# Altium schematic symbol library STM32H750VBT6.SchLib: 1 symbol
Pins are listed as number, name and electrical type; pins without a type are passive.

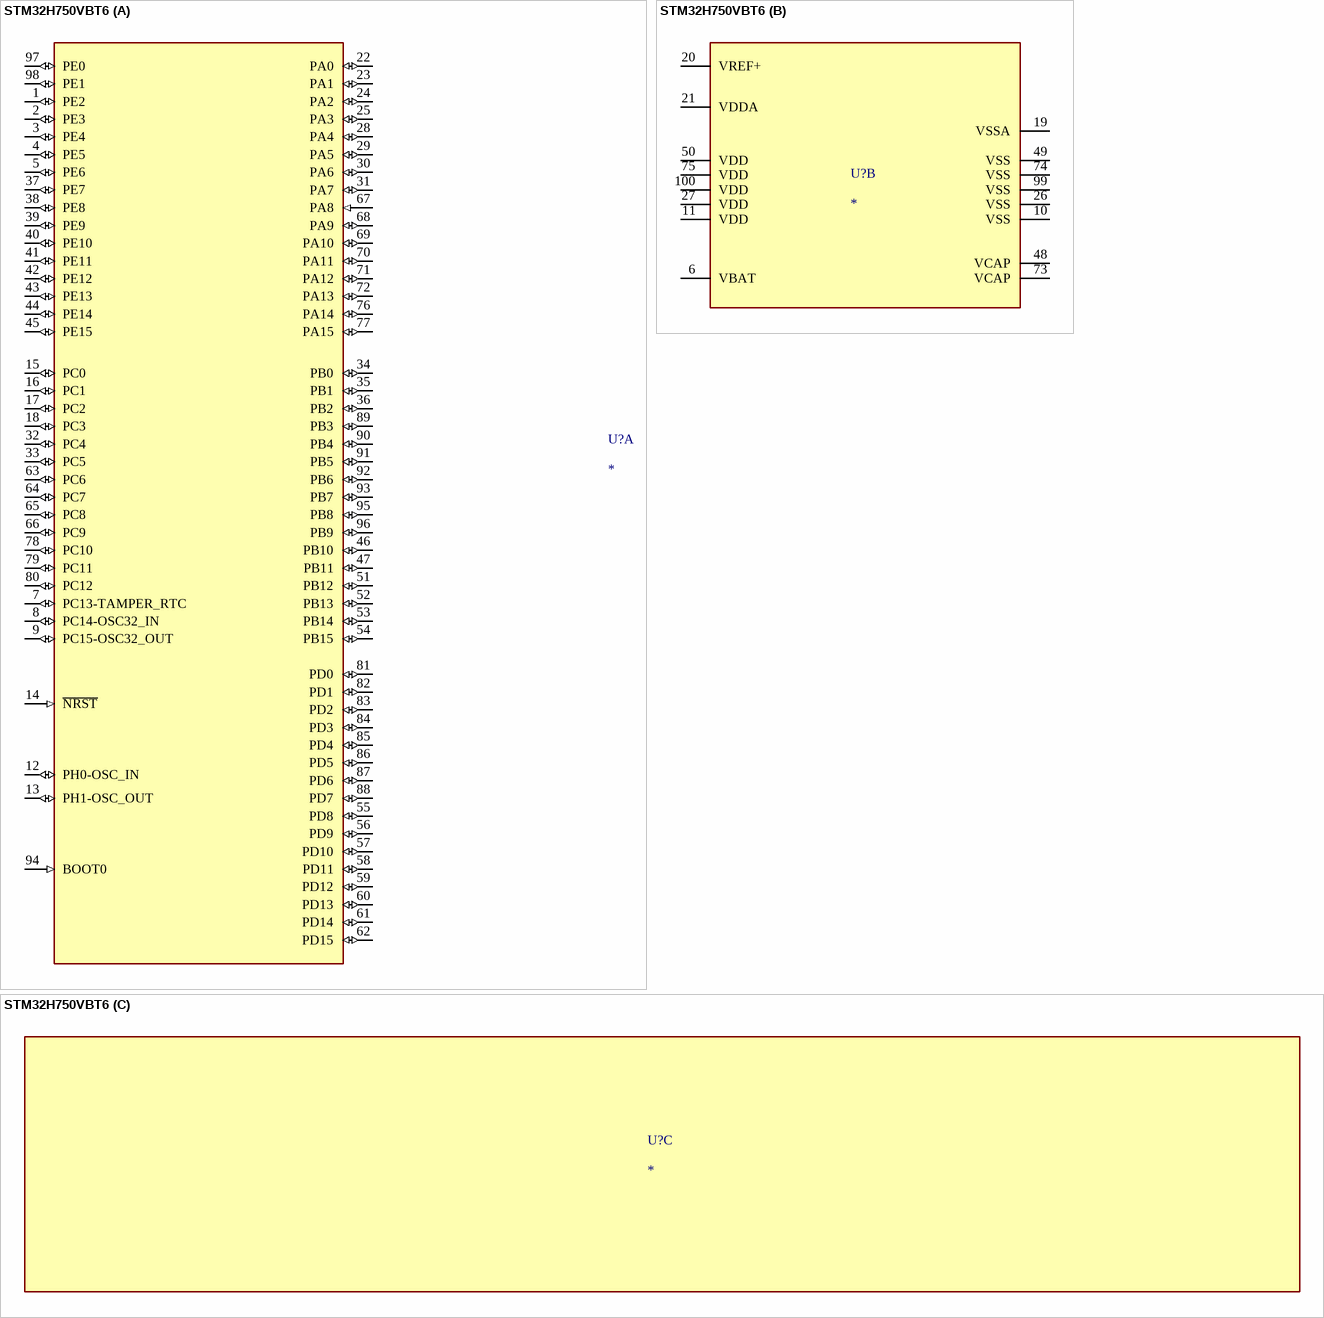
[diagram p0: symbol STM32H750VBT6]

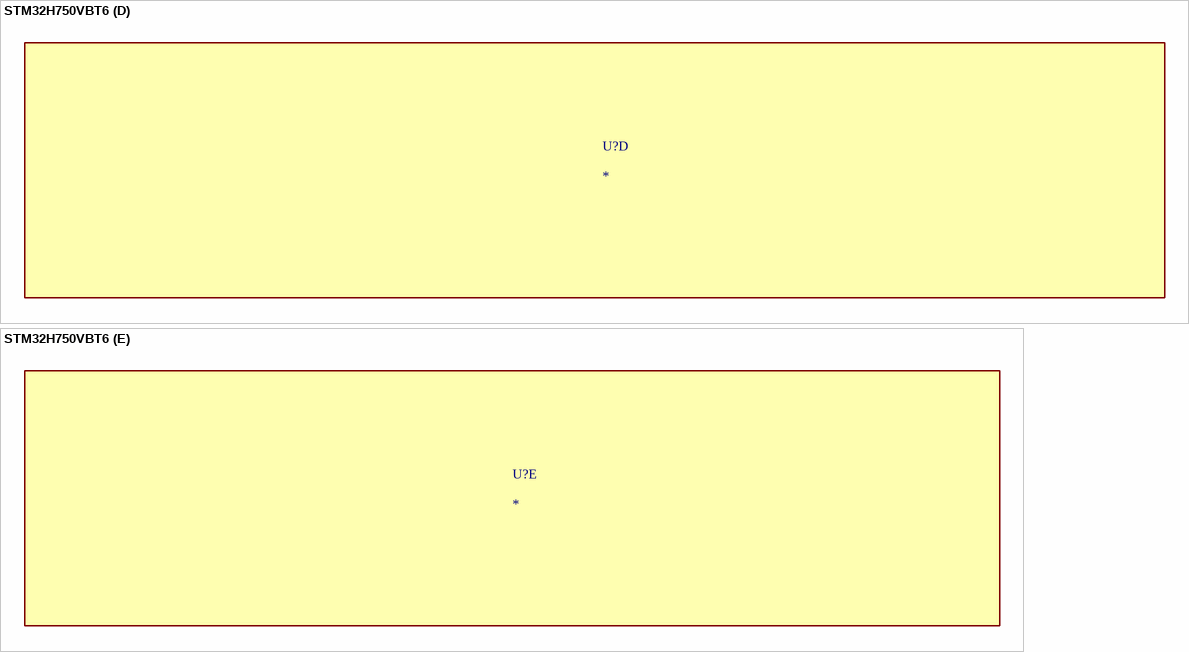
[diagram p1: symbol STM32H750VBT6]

## STM32H750VBT6
designator U?
ARM Cortex-M7 STM32H7 Microcontroller IC 32-Bit 480MHz 128KB _128K x 8_ FLASH 100-LQFP _14x14_; MF: STMicroelectronics; MP: STM32H750VBT6
footprint STM32H750VBT6
part A pins: 1 PE2 (io), 2 PE3 (io), 3 PE4 (io), 4 PE5 (io), 5 PE6 (io), 7 PC13-TAMPER_RTC (io), 8 PC14-OSC32_IN (io), 9 PC15-OSC32_OUT (io), 12 PH0-OSC_IN (io), 13 PH1-OSC_OUT (io), 14 ~{NRST} (in), 15 PC0 (io), 16 PC1 (io), 17 PC2 (io), 18 PC3 (io), 22 PA0 (io), 23 PA1 (io), 24 PA2 (io), 25 PA3 (io), 28 PA4 (io), 29 PA5 (io), 30 PA6 (io), 31 PA7 (io), 32 PC4 (io), 33 PC5 (io), 34 PB0 (io), 35 PB1 (io), 36 PB2 (io), 37 PE7 (io), 38 PE8 (io), 39 PE9 (io), 40 PE10 (io), 41 PE11 (io), 42 PE12 (io), 43 PE13 (io), 44 PE14 (io), 45 PE15 (io), 46 PB10 (io), 47 PB11 (io), 51 PB12 (io), 52 PB13 (io), 53 PB14 (io), 54 PB15 (io), 55 PD8 (io), 56 PD9 (io), 57 PD10 (io), 58 PD11 (io), 59 PD12 (io), 60 PD13 (io), 61 PD14 (io), 62 PD15 (io), 63 PC6 (io), 64 PC7 (io), 65 PC8 (io), 66 PC9 (io), 67 PA8 (in), 68 PA9 (io), 69 PA10 (io), 70 PA11 (io), 71 PA12 (io), 72 PA13 (io), 76 PA14 (io), 77 PA15 (io), 78 PC10 (io), 79 PC11 (io), 80 PC12 (io), 81 PD0 (io), 82 PD1 (io), 83 PD2 (io), 84 PD3 (io), 85 PD4 (io), 86 PD5 (io), 87 PD6 (io), 88 PD7 (io), 89 PB3 (io), 90 PB4 (io), 91 PB5 (io), 92 PB6 (io), 93 PB7 (io), 94 BOOT0 (in), 95 PB8 (io), 96 PB9 (io), 97 PE0 (io), 98 PE1 (io)
part B pins: 6 VBAT (power), 10 VSS (power), 11 VDD (power), 19 VSSA (power), 20 VREF+ (power), 21 VDDA (power), 26 VSS (power), 27 VDD (power), 48 VCAP (power), 49 VSS (power), 50 VDD (power), 73 VCAP (power), 74 VSS (power), 75 VDD (power), 99 VSS (power), 100 VDD (power)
